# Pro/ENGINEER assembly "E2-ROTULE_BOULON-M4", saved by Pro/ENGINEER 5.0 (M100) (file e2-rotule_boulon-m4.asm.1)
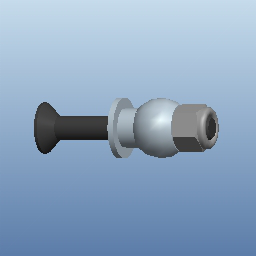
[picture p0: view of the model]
Units: millimeter Newton Second (mmNs); MM, TONNE, HOURS

Other components: 02-ROTULE_STD_S01, ECROU_H_FR_M4, RONDELLE_PLATE-D4, VIS_FHC_M4X30

Other named items: 02-ROTULE_STD_V11, A-DROITE, A-DESSUS, A-FACE, A-R0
